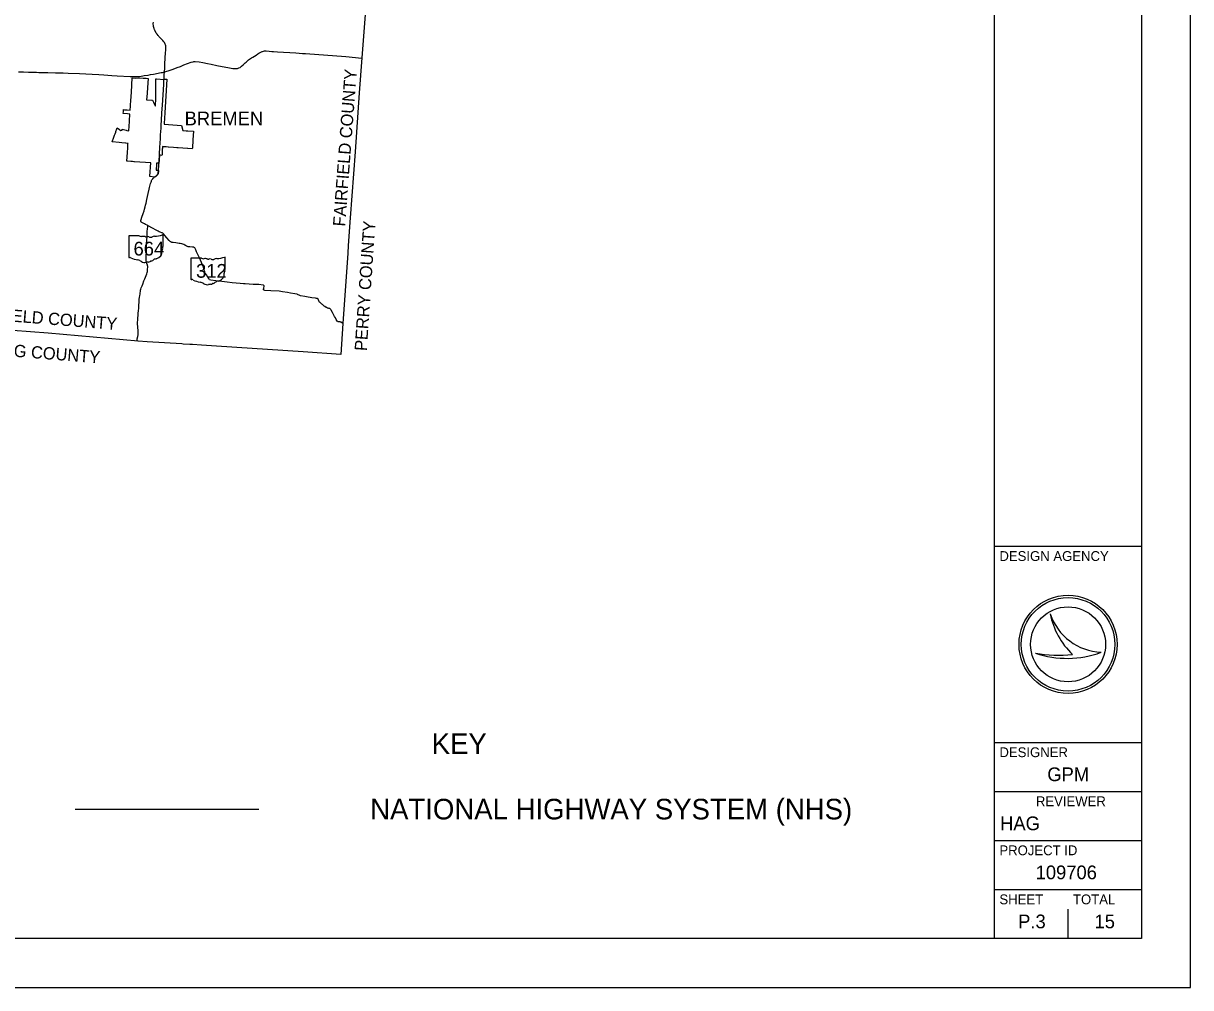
# Model space of a CAD drawing. Extents: x 1801177 to 2073177, y 551183 to 727183.
# Drawn here: x 1977949 to 2073177, y 551183 to 629829 of the extents above; entities that cross this region are included whole.
import ezdxf

# ---------------------------------------------------------------- set-up
doc = ezdxf.new("R2010")
doc.units = 0
for name, color, linetype in [('GM_X_Corporation', 7, 'Continuous'), ('GM_X_Corporation_Text', 7, 'Continuous'), ('GM_X_County', 7, 'Continuous'), ('GM_X_County_Text', 7, 'Continuous'), ('GM_X_State_Location', 7, 'Continuous'), ('GM_X_State_Route', 7, 'Continuous'), ('GM_X_State_Shield', 7, 'Continuous'), ('SH_Border', 7, 'Continuous'), ('SH_Cut_Line', 7, 'Continuous'), ('SH_Data', 7, 'Continuous'), ('UT_P_Electric', 7, 'Continuous')]:
    doc.layers.add(name, color=color, linetype=linetype)

msp = doc.modelspace()

# ---------------------------------------------------------------- linework, layer by layer
at = {"layer": 'GM_X_Corporation'}
msp.add_lwpolyline([(1988340, 618454), (1987024, 618539), (1986990, 618541), (1986971, 618542), (1986852, 618551), (1986707, 618561), (1986449, 618579), (1986419, 618581), (1986419, 618582), (1986419, 618584), (1986399, 618582), (1986403, 618671), (1986411, 618869), (1986422, 619030), (1986435, 619213), (1986449, 619392), (1986460, 619576), (1986485, 620013), (1986487, 620031), (1986487, 620037), (1986486, 620037), (1986322, 620051), (1986278, 620055), (1985970, 620085), (1985766, 620105), (1985183, 620162), (1985318, 620536), (1985324, 620550), (1985379, 620702), (1985400, 620757), (1985430, 620831), (1985481, 620962), (1985503, 621018), (1985534, 621099), (1985551, 621146), (1985608, 621296), (1985804, 621163), (1985817, 621155), (1985896, 621100), (1985982, 621117), (1985985, 621077), (1986020, 621206), (1986238, 621131), (1986336, 621122), (1986405, 621101), (1986553, 621055), (1986576, 621430), (1986604, 621816), (1986616, 622003), (1986621, 622074), (1986631, 622230), (1986635, 622283), (1986643, 622412), (1986645, 622432), (1986616, 622434), (1986450, 622447), (1986097, 622476), (1986106, 622631), (1986115, 622792), (1986203, 622785), (1986363, 622772), (1986377, 622771), (1986393, 622770), (1986424, 622767), (1986663, 622748), (1986669, 622848), (1986677, 622963), (1986681, 623028), (1986684, 623078), (1986691, 623191), (1986691, 623192), (1986713, 623504), (1986760, 624210), (1986840, 625392), (1986840, 625392), (1987076, 625371), (1987373, 625389), (1987727, 625366), (1987979, 625350), (1988128, 625341), (1988077, 624610), (1988044, 624129), (1988024, 623832), (1988007, 623587), (1988047, 623584), (1988443, 623557), (1988476, 623555), (1988483, 623554), (1988566, 623403), (1988565, 623385), (1988573, 623385), (1988580, 623384), (1988699, 623101), (1988713, 623100), (1988734, 623097), (1988734, 623097), (1988744, 623698), (1988752, 624221), (1988770, 625302), (1988770, 625302), (1988813, 625300), (1989427, 625258), (1989427, 625258), (1989429, 625282), (1989429, 625288), (1989499, 625285), (1989653, 625276), (1989653, 625276), (1989485, 622524), (1989431, 621653), (1989429, 621614), (1990857, 621511), (1990959, 621091), (1991227, 621072), (1991376, 621063), (1991380, 621062), (1991822, 621034), (1991780, 620340), (1991739, 619652), (1991725, 619590), (1991375, 619617), (1991332, 619620), (1990583, 619677), (1990483, 619683), (1990471, 619684), (1990195, 619705), (1989777, 619737), (1989765, 619738), (1989592, 619751), (1989580, 619752), (1989530, 619756), (1989518, 619757), (1989475, 619760), (1989414, 619765), (1989409, 619765), (1989389, 619767), (1989376, 619768), (1989299, 619774), (1989299, 619765), (1989296, 619711), (1989294, 619678), (1989292, 619654), (1989287, 619570), (1989286, 619543), (1989272, 619303), (1989262, 619134), (1989258, 619056), (1989133, 619066), (1989046, 619072), (1989025, 618707), (1989024, 618699), (1989021, 618640), (1989019, 618613), (1989018, 618595), (1989016, 618560), (1989012, 618501), (1989011, 618491), (1989008, 618440), (1989007, 618419), (1989007, 618411), (1988930, 618416), (1988807, 618424), (1988807, 618424), (1988803, 618365), (1988801, 618322), (1988772, 617855), (1988911, 617845), (1988971, 617841), (1988971, 617841), (1988966, 617749), (1988962, 617687), (1988962, 617685), (1988962, 617684), (1988962, 617684), (1988962, 617684), (1988962, 617683), (1988961, 617682), (1988961, 617682), (1988961, 617682), (1988961, 617681), (1988961, 617680), (1988961, 617679), (1988961, 617678), (1988958, 617649), (1988952, 617621), (1988944, 617593), (1988934, 617565), (1988922, 617539), (1988908, 617513), (1988892, 617489), (1988874, 617466), (1988854, 617445), (1988833, 617425), (1988811, 617406), (1988663, 617296), (1988268, 617331), (1988268, 617336), (1988270, 617362)], close=True, dxfattribs=at)
at = {"layer": 'GM_X_County'}
msp.add_lwpolyline([(2005845, 630559), (2005566, 627003), (2005354, 624172), (2005008, 619347), (2004609, 613967), (2004446, 611711), (2004409, 611078), (2004013, 605355), (2003837, 602826), (2000786, 603026), (1993695, 603490), (1992479, 603593), (1991738, 603625), (1991697, 603638), (1991650, 603642), (1991603, 603640), (1991519, 603633), (1990990, 603670), (1990885, 603680), (1990876, 603680), (1988048, 603860), (1987314, 603917), (1979976, 604550), (1972730, 605097)], dxfattribs=at)
at = {"layer": 'GM_X_State_Route'}
for p, q in [((1977541, 625881), (1977961, 625877)), ((1989461, 625868), (1989479, 626182)), ((1989461, 625868), (1989768, 625958)), ((1989422, 625245), (1989425, 625297))]:
    msp.add_line(p, q, dxfattribs=at)
for points in [[(1988973, 628804), (1988936, 628844), (1988860, 628936), (1988795, 629036), (1988744, 629118), (1988661, 629313), (1988629, 629400), (1988580, 629563), (1988556, 629650), (1988548, 629750), (1988549, 629823), (1988559, 629914)], [(1989479, 626182), (1989491, 626387), (1989501, 626535), (1989557, 627463), (1989569, 627608), (1989576, 627756), (1989578, 627831), (1989576, 627908), (1989562, 627987), (1989534, 628090), (1989514, 628144), (1989487, 628207), (1989460, 628255), (1989415, 628322), (1989340, 628419), (1989270, 628496), (1989097, 628664), (1989010, 628764), (1988973, 628804)], [(1990760, 626320), (1991054, 626437), (1991648, 626653), (1991795, 626701), (1991861, 626714), (1991958, 626718), (1992303, 626679), (1992578, 626627), (1992978, 626542), (1993262, 626487), (1993742, 626404), (1994778, 626200), (1995041, 626153), (1995146, 626138), (1995230, 626136), (1995323, 626140), (1995430, 626156), (1995520, 626188), (1995639, 626238), (1995759, 626330), (1995876, 626439), (1996046, 626609), (1996116, 626666), (1996242, 626785), (1996327, 626854), (1996556, 627004), (1996677, 627082), (1996934, 627245), (1997075, 627334), (1997171, 627392), (1997318, 627486), (1997424, 627524), (1997470, 627542), (1997622, 627575), (1997764, 627577), (1998012, 627568), (1998218, 627543), (1998348, 627539), (1998686, 627514), (2000176, 627419), (2000724, 627381), (2000957, 627367), (2004264, 627127), (2005568, 627001)], [(1977961, 625877), (1978358, 625861), (1978723, 625851), (1979030, 625836), (1979211, 625832), (1979766, 625822), (1979953, 625812), (1980585, 625802), (1981190, 625784), (1981601, 625764), (1982524, 625748), (1983553, 625692), (1984097, 625657), (1984527, 625624), (1985164, 625576), (1985604, 625547), (1986671, 625487), (1986961, 625482), (1987249, 625489), (1987464, 625504), (1987818, 625564), (1988127, 625612), (1988322, 625647), (1988573, 625695), (1989205, 625812)], [(1989205, 625812), (1989294, 625828), (1989461, 625868)], [(1989443, 625556), (1989449, 625639), (1989461, 625868)], [(1989768, 625958), (1989834, 625977), (1989928, 626008), (1990173, 626095), (1990506, 626219), (1990760, 626320)], [(1989223, 621917), (1989259, 622539), (1989300, 623160), (1989399, 624833), (1989422, 625245)], [(1989425, 625297), (1989426, 625307), (1989443, 625556)], [(1989200, 621555), (1989222, 621902), (1989223, 621917)], [(1989147, 620723), (1989182, 621270), (1989200, 621555)], [(1989094, 619840), (1989100, 619939), (1989107, 620048)], [(1989107, 620048), (1989132, 620451), (1989144, 620666), (1989147, 620723)], [(1989011, 618471), (1989017, 618581), (1989049, 619099), (1989091, 619787), (1989094, 619840)], [(1988103, 613327), (1988100, 613332), (1988096, 613338), (1988088, 613344), (1988077, 613352), (1988050, 613367), (1987924, 613433), (1987821, 613484), (1987675, 613553), (1987626, 613577), (1987607, 613589), (1987587, 613605), (1987571, 613620), (1987559, 613637), (1987549, 613654), (1987543, 613667), (1987539, 613680), (1987536, 613692), (1987535, 613707), (1987535, 613718), (1987535, 613732), (1987537, 613746), (1987541, 613762), (1987545, 613777), (1987550, 613795), (1987564, 613843), (1987627, 614030), (1987723, 614309), (1987798, 614543), (1987841, 614684), (1987894, 614874), (1987927, 615001), (1987963, 615161), (1988029, 615466), (1988130, 615964), (1988206, 616317), (1988233, 616429), (1988268, 616556), (1988330, 616760), (1988371, 616885), (1988398, 616962), (1988417, 617008), (1988439, 617053), (1988463, 617096), (1988481, 617124), (1988500, 617151), (1988522, 617176), (1988545, 617200), (1988582, 617232), (1988634, 617272), (1988780, 617379), (1988818, 617410), (1988853, 617442), (1988865, 617455), (1988876, 617466), (1988896, 617492), (1988913, 617519), (1988920, 617534), (1988927, 617548), (1988939, 617579), (1988947, 617610), (1988951, 617626), (1988954, 617642), (1988961, 617690), (1988970, 617788), (1988974, 617838), (1988980, 617935), (1988993, 618171), (1989011, 618471)], [(1987315, 603915), (1987269, 603938), (1987241, 603965), (1987230, 603990), (1987228, 604014), (1987230, 604049), (1987241, 604106), (1987288, 604280), (1987305, 604419), (1987312, 604529), (1987319, 604638), (1987317, 604726), (1987308, 604830), (1987294, 604958), (1987281, 605094), (1987255, 605303), (1987252, 605367), (1987260, 605469), (1987277, 605619), (1987297, 605805), (1987315, 606011), (1987327, 606199), (1987344, 606369), (1987358, 606600), (1987374, 606853), (1987394, 607079), (1987404, 607325), (1987418, 607479), (1987446, 607627), (1987468, 607734), (1987481, 607847), (1987493, 607969), (1987508, 608058), (1987541, 608163), (1987570, 608257), (1987641, 608418), (1987692, 608564), (1987787, 608826), (1987814, 608892), (1987854, 608995), (1987913, 609123), (1987973, 609251), (1988023, 609390), (1988062, 609514), (1988082, 609594), (1988087, 609656), (1988088, 609761), (1988095, 609983), (1988095, 610012), (1988087, 610046), (1988067, 610099), (1988016, 610235), (1987994, 610309), (1987983, 610359), (1987976, 610405), (1987971, 610511), (1987975, 610712), (1987974, 610888), (1987989, 611159), (1987991, 611415), (1988009, 611849), (1988047, 612438), (1988056, 612599), (1988062, 612884), (1988074, 613032), (1988085, 613096), (1988097, 613211), (1988106, 613282), (1988107, 613312), (1988103, 613327)], [(1997584, 608428), (1997554, 608465), (1997510, 608488), (1997163, 608541), (1997034, 608543), (1996972, 608537), (1996936, 608522), (1996867, 608519), (1996691, 608530), (1996361, 608557), (1996057, 608587), (1995917, 608597), (1995642, 608616), (1994985, 608667), (1994579, 608714), (1993932, 608801), (1993655, 608835), (1993255, 608880), (1993148, 608899), (1993071, 609012), (1993000, 609129), (1992882, 609319), (1992806, 609417), (1992763, 609494), (1992748, 609569), (1992738, 609656), (1992712, 609741), (1992684, 609815), (1992641, 609938), (1992584, 610078), (1992484, 610328), (1992408, 610523), (1992317, 610703), (1992247, 610858), (1992085, 611191), (1992022, 611348), (1991989, 611423), (1991937, 611518), (1991898, 611554), (1991870, 611571), (1991829, 611583), (1991748, 611587), (1991524, 611599), (1991403, 611610), (1991340, 611625), (1991255, 611665), (1991178, 611705), (1991112, 611743), (1991029, 611782), (1990873, 611840), (1990749, 611873), (1990669, 611887), (1990512, 611911), (1990399, 611926), (1990172, 611950), (1990063, 611967), (1990034, 611975), (1990005, 611986), (1989970, 612006), (1989938, 612033), (1989857, 612127), (1989668, 612330), (1989502, 612525), (1989408, 612627), (1989354, 612681), (1989320, 612710), (1989287, 612732), (1989241, 612754), (1989117, 612803), (1989026, 612839), (1988940, 612880), (1988775, 612967), (1988475, 613138), (1988139, 613318), (1988120, 613324), (1988103, 613327)], [(1997536, 608085), (1997554, 608158), (1997572, 608241), (1997587, 608396), (1997584, 608428)], [(2001195, 607500), (2000917, 607550), (2000562, 607611), (2000504, 607629), (2000462, 607648), (2000382, 607693), (2000325, 607719), (2000280, 607732), (2000086, 607776), (1999746, 607834), (1999492, 607879), (1999090, 607945), (1998961, 607965), (1998816, 607988), (1998142, 608016), (1997648, 608046), (1997584, 608059), (1997536, 608085)], [(2001487, 607446), (2001345, 607476), (2001195, 607500)], [(2004014, 605352), (2003915, 605436), (2003866, 605457), (2003851, 605463), (2003827, 605469), (2003802, 605472), (2003753, 605474), (2003705, 605474), (2003673, 605476), (2003647, 605480), (2003626, 605483), (2003594, 605500), (2003553, 605551), (2003475, 605689), (2003402, 605816), (2003330, 605931), (2003215, 606150), (2003165, 606240), (2003065, 606425), (2003032, 606480), (2003004, 606516), (2002980, 606544), (2002969, 606555), (2002949, 606564), (2002914, 606575), (2002880, 606586), (2002816, 606599), (2002755, 606613), (2002672, 606645), (2002641, 606660), (2002545, 606729), (2002494, 606773), (2002441, 606818), (2002367, 606886), (2002301, 606934), (2002217, 606997), (2002152, 607049), (2002118, 607083), (2002093, 607118), (2002054, 607200), (2002026, 607274), (2002012, 607316), (2001994, 607351), (2001970, 607372), (2001946, 607381), (2001875, 607391), (2001771, 607406), (2001487, 607446)]]:
    msp.add_lwpolyline(points, dxfattribs=at)
at = {"layer": 'GM_X_State_Shield'}
for p, q in [((1986542, 612475), (1986542, 610774)), ((1987390, 612505), (1986569, 612505)), ((1989343, 611657), (1989343, 612547)), ((1989343, 611657), (1989343, 611657)), ((1991623, 610661), (1991623, 608960)), ((1992471, 610690), (1991651, 610690)), ((1994425, 609843), (1994425, 610732)), ((1994425, 609843), (1994425, 609843))]:
    msp.add_line(p, q, dxfattribs=at)
for centre, major_axis, start_param, end_param in [((1986574, 612479), (32.5, 0), 1.712693, 3.28349), ((1987585, 612702), (315, 0), 4.042523, 4.731795), ((1987689, 611550), (1130, 0), 1.404758, 1.657858), ((1987946, 612488), (90.8, 0), 3.836095, 5.185415), ((1988079, 612291), (189, 0), 0.950623, 2.079405), ((1988323, 612561), (227, 0), 4.081561, 5.145723), ((1988724, 611985), (598, 0), 1.699011, 2.107814), ((1988345, 614824), (2971, 0), 4.814394, 5.042369), ((1989312, 612551), (31.2, 0), 6.141152, 7.989035), ((1989455, 611285), (211, 0), 2.387724, 3.262537), ((1989336, 611592), (48.3, 0), 1.883978, 3.671073), ((1989029, 611479), (290, 0), 5.934695, 6.695948), ((1989310, 611654), (33.4, 0), 5.05454, 6.418171), ((1986574, 610771), (32.7, 0), 3.00124, 4.508301), ((1986579, 610945), (250, 0), 4.665946, 4.897461), ((1986630, 610676), (90.1, 0), 0.519207, 1.627899), ((1987768, 612205), (2146, 0), 4.195997, 4.488961), ((1987128, 610010), (671, 0), 0.823519, 1.323587), ((1988131, 610540), (227, 0), 4.691044, 5.507374), ((1988337, 610376), (63.9, 0), 1.147584, 2.315152), ((1988309, 610609), (240, 0), 4.937069, 5.64225), ((1988825, 610297), (407, 0), 1.647645, 2.488434), ((1988512, 611171), (743, 0), 5.101752, 6.440018), ((1991655, 610665), (32.5, 0), 1.712693, 3.28349), ((1992667, 610888), (315, 0), 4.042523, 4.731795), ((1992771, 609735), (1130, 0), 1.404758, 1.657858), ((1993028, 610673), (90.8, 0), 3.836095, 5.185415), ((1993161, 610477), (189, 0), 0.950623, 2.079405), ((1993405, 610747), (227, 0), 4.081561, 5.145723), ((1993806, 610171), (598, 0), 1.699011, 2.107814), ((1993427, 613010), (2971, 0), 4.814394, 5.042369), ((1994394, 610736), (31.2, 0), 6.141152, 7.989035), ((1987854, 610668), (426, 0), 4.026481, 4.996735), ((1988100, 610080), (350, 0), 1.495662, 1.94098), ((1994537, 609470), (211, 0), 2.387724, 3.262537), ((1994418, 609777), (48.3, 0), 1.883978, 3.671073), ((1994111, 609665), (290, 0), 5.934695, 6.695948), ((1994392, 609839), (33.4, 0), 5.05454, 6.418171), ((1991656, 608956), (32.7, 0), 3.00124, 4.508301), ((1991661, 609130), (250, 0), 4.665946, 4.897461), ((1991712, 608862), (90.1, 0), 0.519207, 1.627899), ((1992849, 610390), (2146, 0), 4.195997, 4.488961), ((1992210, 608196), (671, 0), 0.823519, 1.323587), ((1992936, 608853), (426, 0), 4.026481, 4.996735), ((1993182, 608265), (350, 0), 1.495662, 1.94098), ((1993213, 608726), (227, 0), 4.691044, 5.507374), ((1993418, 608561), (63.9, 0), 1.147584, 2.315152), ((1993391, 608795), (240, 0), 4.937069, 5.64225), ((1993907, 608482), (407, 0), 1.647645, 2.488434), ((1993593, 609357), (743, 0), 5.101752, 6.440018)]:
    msp.add_ellipse(centre, major_axis=major_axis, ratio=0.8, start_param=start_param, end_param=end_param, dxfattribs=at)
at = {"layer": 'SH_Border'}
for p, q in [((2057177, 555183), (2057177, 723183)), ((2057177, 587183), (2069177, 587183)), ((2057177, 571183), (2069177, 571183)), ((2057177, 567183), (2069177, 567183)), ((2057177, 563183), (2069177, 563183)), ((2057177, 559183), (2069177, 559183))]:
    msp.add_line(p, q, dxfattribs=at)
msp.add_lwpolyline([(1813177, 723183), (2069177, 723183), (2069177, 555183), (1813177, 555183)], close=True, dxfattribs=at)
at = {"layer": 'SH_Cut_Line'}
msp.add_lwpolyline([(1801177, 551183), (2073177, 551183), (2073177, 727183), (1801177, 727183)], close=True, dxfattribs=at)
at = {"layer": 'SH_Data'}
for p, q in [((2061717, 581660), (2061717, 581660)), ((2063177, 579183), (2063177, 579183)), ((2060514, 578459), (2060514, 578459)), ((2065875, 578531), (2065875, 578531)), ((2063177, 555183), (2063177, 557583)), ((2060177, 556583), (2060177, 556583))]:
    msp.add_line(p, q, dxfattribs=at)
for radius in [4000, 3814, 3814, 3058]:
    msp.add_circle((2063177, 579183), radius, dxfattribs=at)
for centre, radius, start, end in [((2066105, 583164), 4639, 198.92567, 198.93195), ((2067950, 582944), 6365, 191.63793, 191.64215), ((2066105, 583164), 4639, 198.93195, 267.16574), ((2067950, 582944), 6365, 191.64215, 226.09467), ((2062361, 588418), 10128, 259.49639, 259.49952), ((2063092, 586143), 8105, 251.45274, 251.45764), ((2063092, 586143), 8105, 251.45764, 290.08324), ((2062361, 588418), 10128, 259.49952, 276.66723)]:
    msp.add_arc(centre, radius, start, end, dxfattribs=at)
at = {"layer": 'UT_P_Electric'}
msp.add_line((1982166, 565743), (1997166, 565743), dxfattribs=at)

# ---------------------------------------------------------------- texts
at = {"layer": 'GM_X_Corporation_Text'}
msp.add_text('BREMEN', height=1120, rotation=0.00001, dxfattribs=at).set_placement((1991106, 621512))
at = {"layer": 'GM_X_County_Text'}
for s, rotation, p in [('FAIRFIELD COUNTY', 85.68928, (2004198, 613239)), ('PERRY COUNTY', 86.11607, (2005964, 603085)), ('FAIRFIELD COUNTY', 355.46053, (1972751, 605838)), ('HOCKING COUNTY', 355.51045, (1971952, 603053))]:
    msp.add_text(s, height=1000, rotation=rotation, dxfattribs=at).set_placement(p)
at = {"layer": 'GM_X_State_Location'}
for s, p in [('664', (1987621, 612136)), ('312', (1992395, 609391))]:
    msp.add_text(s, height=1, rotation=0.00001, dxfattribs=at).set_placement(p)
for s, p in [('s', (1987974, 612209)), ('r', (1987974, 612209)), ('s', (1992748, 609463)), ('r', (1992748, 609463))]:
    msp.add_text(s, height=1, dxfattribs=at).set_placement(p)
at = {"layer": 'GM_X_State_Shield'}
for s, p in [('664', (1986937, 610894)), ('312', (1992040, 609080))]:
    msp.add_text(s, height=1120.7, dxfattribs=at).set_placement(p)
at = {"layer": 'SH_Data'}
for s, height, p in [('DESIGN AGENCY', 800, (2057577, 585983)), ('DESIGNER', 800, (2057577, 569983)), ('GPM', 1120, (2061484, 568023)), ('REVIEWER', 800, (2060552, 565983)), ('HAG', 1120, (2057631, 564023)), ('PROJECT ID', 800, (2057577, 561983)), ('109706', 1120, (2060530, 560023)), ('SHEET', 800, (2057577, 557983)), ('TOTAL', 800, (2063577, 557983)), ('P.3', 1120, (2059105, 556023)), ('15', 1120, (2065335, 556023))]:
    msp.add_text(s, height=height, dxfattribs=at).set_placement(p)
at = {"layer": 'UT_P_Electric'}
for s, p in [('KEY', (2011259, 570251)), ('NATIONAL HIGHWAY SYSTEM (NHS)', (2006246, 564903))]:
    msp.add_text(s, height=1680, dxfattribs=at).set_placement(p)

doc.saveas('drawing.dxf')
